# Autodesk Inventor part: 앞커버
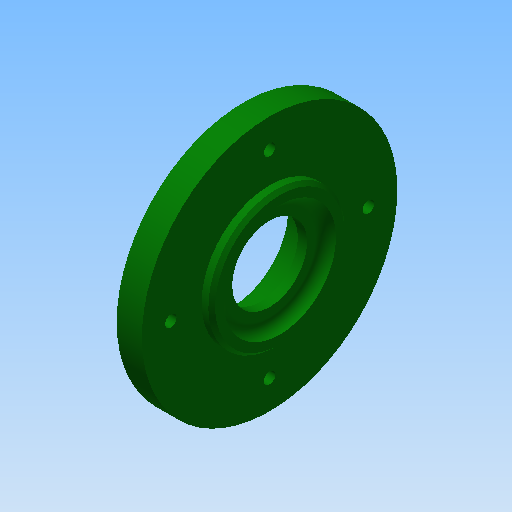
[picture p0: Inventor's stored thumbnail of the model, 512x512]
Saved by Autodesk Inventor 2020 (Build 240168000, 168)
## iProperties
Created: 2015-09
Part Number: 앞커버
Material: 알루미늄 6061
Document SubType Name: Modeling
Designer: mduedu
Density: 2.71 g/cm^3
Mass: 58.9874 g
Surface Area: 98.7754 cm^2
Volume: 21.7666 cm^3
Appearance: 진녹색
Author: mduedu
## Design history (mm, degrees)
sketch "스케치1"
  geometry: L1 (-8.5, 67)-(-11.5, 67); L2 (-11.5, 67)-(-11.5, 84.5); L3 (-11.5, 84.5)-(-19.5, 84.5); L4 (-19.5, 84.5)-(-19.5, 70.5); L5 (-22.5, 70.5)-(-22.5, 58); L6 (-22.5, 58)-(-8.5, 58); L7 (-8.5, 58)-(-8.5, 67); L8 (-79.5, 39.5)-(-79.5, 54.5) reference; L9 (48.5, 54.5)-(48.5, 39.5) reference; L10 (-79.5, 47)-(48.5, 47); L11 (-19.5, 70.5)-(-22.5, 70.5); 3 further points
  constraints: 18 end point, 6 parallel, 4 midpoint, 1 horizontal, 1 perpendicular, 1 vertical alignment
  dimensions: "d0" = 14 distance between parallel lines of L7 L5; "d2" = 22 diameter of L6 L10; "d3" = 40 diameter of L1 L10; "d5" = 3 distance of L1.start L1.end; "d6" = 75 diameter of L3 L10; "d7" = 8 distance of L2.end L3.end; "d8" = 47 diameter of L4.end L10
revolve "회전1" sketch "스케치1" stored, may be unused: angle "d4" = 90 deg
sketch "스케치2"
  geometry: C1 r 37.5 at (0, 0) reference; 2 further points
  constraints: 1 coincident
hole "구멍1" sketch "스케치2" at (0, 0) diameter "d11" = 33; stored, may be unused: countersink angle "d15" = 90 deg, drill point angle "d17" = 0 deg; dims "d12" = 6, "d13" = 4, "d14" = 2, "d16" = 3
fillet "모깎기1" dims "d18" = 3
fillet "모깎기2" dims "d19" = 1
sketch "스케치3"
  geometry: C1 r 37.5 at (0, 0) reference; 2 further points
  constraints: 1 coincident
hole "구멍2" sketch "스케치3" at (0, 0) diameter "d20" = 32; stored, may be unused: countersink angle "d24" = 90 deg, drill point angle "d26" = 0 deg; dims "d21" = 6, "d22" = 4, "d23" = 2, "d25" = 8.3
fillet "모깎기3" dims "d27" = 0.4
chamfer "모따기1" distance "d28" = 0.8; stored, may be unused: second distance "d29" = 2, angle "d30" = 30 deg
sketch "스케치7" dims "d56" = 58
  geometry: C1 r 37.5 at (0, 0) reference; 5 further points
  constraints: 2 vertical alignment, 1 coincident, 7 other
  dimensions: "d59" = 360 deg dimension on C1.centre point (0, 29) (derived)
hole "구멍4" sketch "스케치7" at (0, 29), (-29, 0), (0, -29), (29, 0) diameter "d48" = 3.4; stored, may be unused: countersink angle "d52" = 90 deg, drill point angle "d54" = 0 deg; dims "d49" = 6, "d50" = 6.5, "d51" = 3.4, "d53" = 8
chamfer "모따기2" distance "d61" = 1; stored, may be unused: second distance "d62" = 2, angle "d63" = 45 deg
node "솔리드1"
node "참조1"
node "참조2"
